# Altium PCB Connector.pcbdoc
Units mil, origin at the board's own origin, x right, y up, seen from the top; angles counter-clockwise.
Board outline 2701.74 x 1475.68 mil, 2 copper layers (Top Layer, Bottom Layer); 8 components, 8 nets, 28 pads, 18 vias.
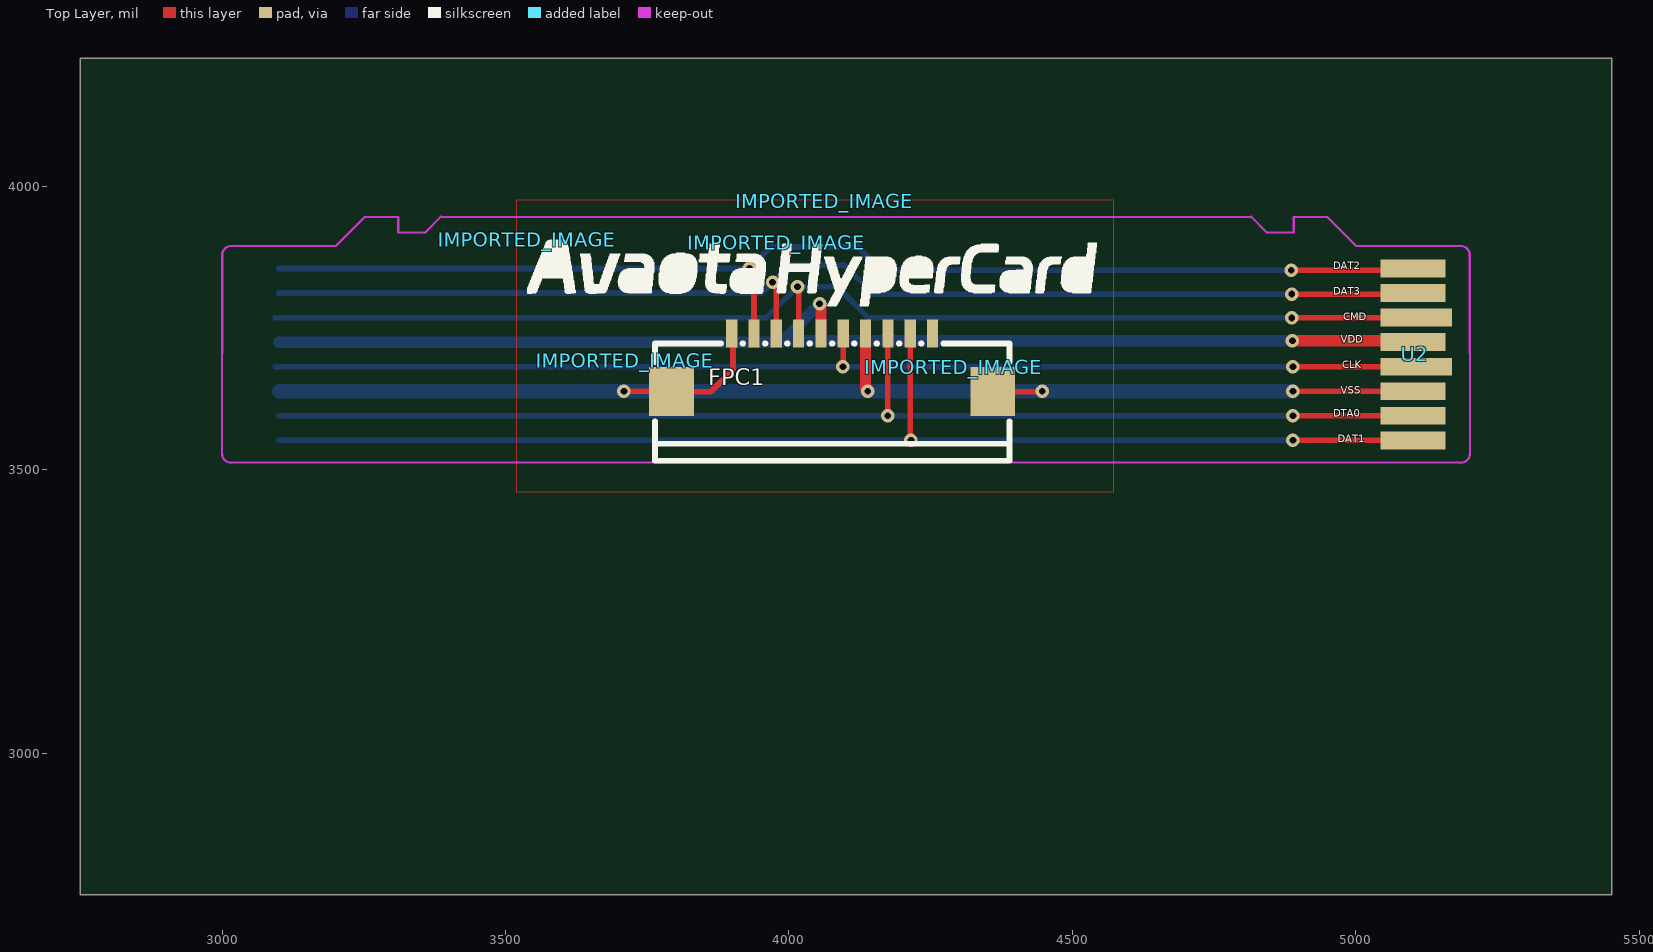
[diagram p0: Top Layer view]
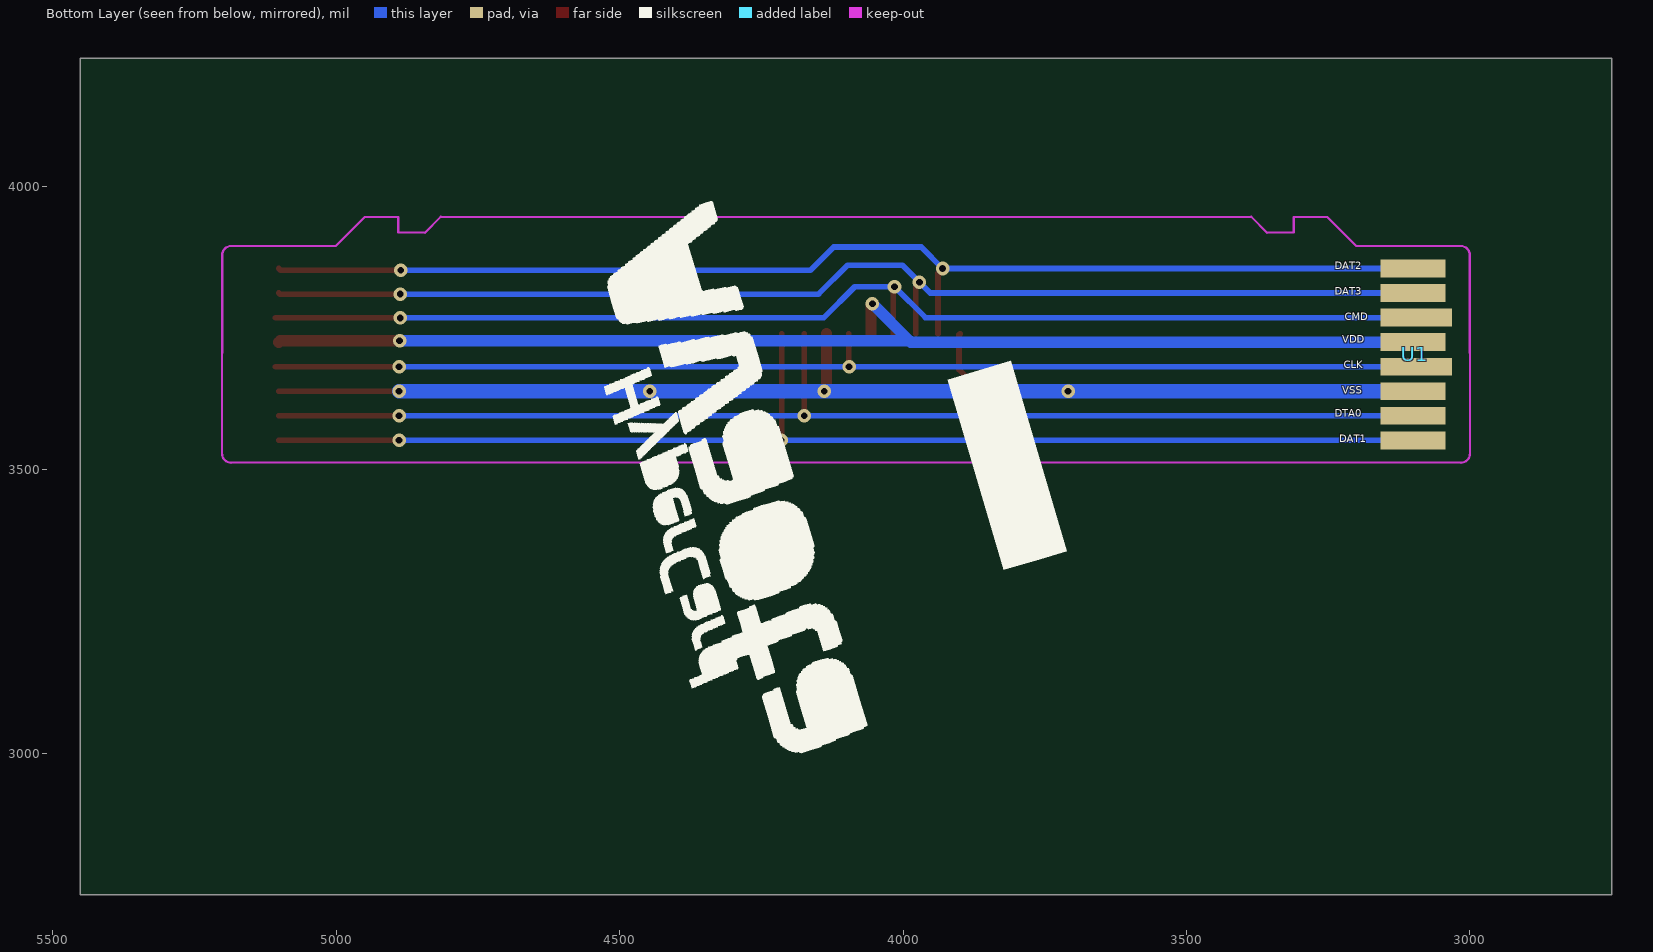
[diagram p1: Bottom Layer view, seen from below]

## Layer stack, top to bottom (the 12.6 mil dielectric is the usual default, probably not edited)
Top Layer: signal copper (thickness not stored)
Dielectric: dielectric 12.6, FR-4, Dk 4.8
Bottom Layer: signal copper (thickness not stored)

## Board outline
5451.74,2750 2750,2750 2750,4225.68 5451.74,4225.68

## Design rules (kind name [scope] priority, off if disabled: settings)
Clearance copperThickness1oz [All] p1: gap=7 ignorepadtopadclearanceinfootprint=FALSE except(4: Track-Track; 6: Track-SMDPad SMDPad-SMDPad Track-THPad SMDPad-THPad THPad-THPad Track-Via SMDPad-Via THPad-Via Via-Via Track-Fill SMDPad-Fill THPad-Fill Via-Fill Fill-Fill SMDPad-Region THPad-Region Via-Region Fill-Region Region-Region Track-Poly SMDPad-Poly THPad-Poly Via-Poly Fill-Poly Poly-Poly Track-Text SMDPad-Text THPad-Text Via-Text Fill-Text Region-Text Poly-Text Text-Text; 6.9: Track-Hole SMDPad-Hole THPad-Hole Via-Hole Fill-Hole Region-Hole Poly-Hole Text-Hole Sheet-Hole; 11.8: Track-Region Region-Poly Track-Sheet SMDPad-Sheet THPad-Sheet Via-Sheet Fill-Sheet Region-Sheet Poly-Sheet Text-Sheet)
Clearance copperThickness2oz [All] p1: gap=7 ignorepadtopadclearanceinfootprint=FALSE except(6: Track-SMDPad SMDPad-SMDPad Track-THPad SMDPad-THPad THPad-THPad Track-Via SMDPad-Via THPad-Via Via-Via Track-Fill SMDPad-Fill THPad-Fill Via-Fill Fill-Fill SMDPad-Region THPad-Region Via-Region Fill-Region Region-Region Track-Poly SMDPad-Poly THPad-Poly Via-Poly Fill-Poly Poly-Poly Track-Text SMDPad-Text THPad-Text Via-Text Fill-Text Region-Text Poly-Text Text-Text; 6.9: Track-Hole SMDPad-Hole THPad-Hole Via-Hole Fill-Hole Region-Hole Poly-Hole Text-Hole Sheet-Hole; 8: Track-Track; 11.8: Track-Region Region-Poly Track-Sheet SMDPad-Sheet THPad-Sheet Via-Sheet Fill-Sheet Region-Sheet Poly-Sheet Text-Sheet)
DiffPairsRouting differentialPair [All] p1: maxuncoupledlength=10 minlimit=0 maxlimit=5.9843 mostfreqgap=5.9843 toplayer_minwidth=5 toplayer_prefwidth=10 toplayer_maxwidth=100 bottomlayer_minwidth=5 bottomlayer_prefwidth=10 bottomlayer_maxwidth=100
PasteMaskExpansion pasteMaskExpansion [All] p1: expansion=0
PlaneConnect innerPlane [All] p1: planeconnectstyle=Relief reliefexpansion=20 reliefentries=4 reliefconductorwidth=10 reliefairgap=10
PolygonConnect copperRegion [All] p1: connectstyle=Relief reliefentries=4 reliefconductorwidth=10 polygonreliefangle="90 Angle" airgapwidth=10
RoutingVias viaSize [All] p1: viastyle="Through Hole" holewidth=12.0078 minholewidth=11.811 maxholewidth=248.0316 width=24.0158 minwidth=19.685 maxwidth=393.7008
SolderMaskExpansion solderMaskExpansion [All] p1: useseparateexpansions=TRUE expansion=2.0079 expansionbottom=2.0079
Width copperThickness1oz [All] p1: maxlimit=100 minlimit=5 preferedwidth=10
Width copperThickness2oz [All] p1: maxlimit=100 minlimit=8 preferedwidth=10

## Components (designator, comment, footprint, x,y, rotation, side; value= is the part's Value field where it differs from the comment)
FPC1 "AFA01-S10FCC-00" FPC-SMD_AFA01-S10FCC-00 4076.37,3688.68 r0 top
IMPORTED_IMAGE "IMPORTED_IMAGE" IMPORTED_IMAGE 4063.67,3973.48 r0 top
IMPORTED_IMAGE "IMPORTED_IMAGE" IMPORTED_IMAGE 4290.94,3680.39 r0 top
IMPORTED_IMAGE "IMPORTED_IMAGE" IMPORTED_IMAGE 3711.13,3691.69 r0 top
IMPORTED_IMAGE "IMPORTED_IMAGE" IMPORTED_IMAGE 3538.37,3905.68 r0 top
IMPORTED_IMAGE "IMPORTED_IMAGE" IMPORTED_IMAGE 3978.37,3900.68 r0 top
U1 "TF Shape" SD卡 3345.37,3731.68 r0 top
U2 "TF Shape" SD卡 4856.37,3731.68 r180 bottom

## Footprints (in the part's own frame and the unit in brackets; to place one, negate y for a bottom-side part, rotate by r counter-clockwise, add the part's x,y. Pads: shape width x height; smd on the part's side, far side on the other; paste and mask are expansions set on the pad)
FPC-SMD_AFA01-S10FCC-00 [mm]
  rect 0.5x1.25 smd: 1(-4.5,1.3) 2(-3.5,1.3) 3(-2.501,1.3) 4(-1.5,1.3) 5(-0.501,1.3) 6(0.499,1.3) 7(1.5,1.3) 8(2.499,1.3) 9(3.5,1.3) 10(4.499,1.3)
  rect 2x2.2 smd: 11(-7.2,-1.3) 12(7.2,-1.3)
  silkscreen extent -7.94,-4.39 7.95,0.86
IMPORTED_IMAGE [mil]
SD卡 [mm]
  rect 2.9x0.8 smd far side: 1(-6.223,3.129) 2(-6.223,2.029) 4(-6.223,-0.171) 6(-6.223,-2.372) 7(-6.223,-3.472) 8(-6.223,-4.572)
  rect 3.2x0.8 smd far side: 3(-6.372,0.928) 5(-6.373,-1.272)
  Board Outline Layer lines w0.1: -8.772,-5.161 -8.762,3.798 -8.772,-5.161 ; -8.372,-5.571 5.868,-5.562 -8.372,-5.571 ; 0.325,4.735 1.034,5.444 0.325,4.735 ; 1.028,5.438 5.828,5.438 1.028,5.438
  Board Outline Layer lines w0.102: -8.772,-5.162 -8.772,-5.062 -8.772,-5.162 ; -8.772,-5.162 ccw(c-8.364,-5.163) -8.372,-5.572 cw(c-8.364,-5.163) -8.772,-5.162 ; -2.372,5.439 -0.871,5.439 ; -2.372,5.439 -0.871,5.439 ; -2.372,5.439 -3.673,4.138 -2.372,5.439 ; -0.871,5.439 -0.871,4.738 -0.871,5.439 ; -8.762,3.738 cw(c-8.362,3.738) -8.362,4.138 ccw(c-8.362,3.738) -8.762,3.738 ; -8.372,4.138 -3.672,4.138 -8.372,4.138 ; -0.873,4.737 0.326,4.737 -0.873,4.737

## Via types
v1: diameter 24.02, hole 12.01, Top Layer to Bottom Layer, 18 vias

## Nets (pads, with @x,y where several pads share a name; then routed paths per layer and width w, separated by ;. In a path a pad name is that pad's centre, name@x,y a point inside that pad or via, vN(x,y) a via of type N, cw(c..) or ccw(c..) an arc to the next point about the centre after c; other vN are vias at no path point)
GND: FPC1.1 FPC1.7 FPC1.11 FPC1.12 U1.6 U2.6 | length 2464.8
  Top Layer w10: v1(3709.02,3638.28) 3792.12,3638.28 FPC1.11 3862.19,3637.5 3901.37,3676.68 3901.37,3737.7 FPC1.1 ; FPC1.12 4446.32,3637.5 v1(4447.11,3638.28) ; v1(4889.37,3638.28) U2.6
  Top Layer w20: FPC1.7 4135.42,3642.24 v1(4139.37,3638.28)
  Bottom Layer w25: U1.6 v1(3709.02,3638.28) v1(4139.37,3638.28) v1(4447.11,3638.28) v1(4889.37,3638.28)
SDC-TF-CLK: FPC1.6 U1.5 U2.5 | length 2071.4
  Top Layer w10: v1(4095.37,3681.68) 4096.02,3682.32 FPC1.6 ; v1(4889.37,3681.68) 5107.19,3681.68 U2.5
  Bottom Layer w10: U1.5 4095.27,3681.58 v1(4095.37,3681.68) v1(4889.37,3681.68)
SDC-TF-CMD: FPC1.4 U1.3 U2.3 | length 2141.9
  Top Layer w10: v1(4015.37,3822.68) 4017.32,3820.73 FPC1.4 ; v1(4887.37,3767.68) 5106.71,3767.68 U2.3
  Bottom Layer w10: U1.3 3960.9,3768.21 v1(4015.37,3822.68) 4085.37,3822.68 4140.37,3767.68 v1(4887.37,3767.68)
SDC-TF-D0: FPC1.8 U1.7 U2.7 | length 2146.1
  Top Layer w10: v1(4174.37,3594.97) 4174.77,3595.37 FPC1.8 ; v1(4889.37,3594.97) U2.7
  Bottom Layer w10: U1.7 v1(4174.37,3594.97) v1(4889.37,3594.97)
SDC-TF-D1: FPC1.9 U1.8 U2.8 | length 2189.7
  Top Layer w10: FPC1.9 4214.17,3552.89 v1(4215.37,3551.68) ; v1(4889.37,3551.68) U2.8
  Bottom Layer w10: U1.8 v1(4215.37,3551.68) v1(4889.37,3551.68)
SDC-TF-D2: FPC1.2 U1.1 U2.1 | length 2153.3
  Top Layer w10: v1(3930.37,3854.85) 3938.57,3846.66 FPC1.2 ; v1(4886.37,3851.68) 5098.18,3851.68 U2.1
  Bottom Layer w10: U1.1 v1(3930.37,3854.85) 3968.2,3892.68 4122.37,3892.68 4163.37,3851.68 v1(4886.37,3851.68)
SDC-TF-D3: FPC1.3 U1.2 U2.2 | length 2136.8
  Top Layer w10: v1(3971.37,3830.68) 3977.92,3824.13 FPC1.3 ; v1(4887.37,3809.68) 5099.51,3809.68 U2.2
  Bottom Layer w10: U1.2 3952.24,3811.55 v1(3971.37,3830.68) 4001.37,3860.68 4098.37,3860.68 4149.37,3809.68 v1(4887.37,3809.68)
VCC-CARD: FPC1.5 U1.4 U2.4 | length 2149.2
  Top Layer w20: v1(4054.37,3792.68) 4056.67,3790.38 FPC1.5 ; v1(4888.37,3727.23) 5099.09,3727.23 U2.4
  Bottom Layer w20: U1.4 3986.65,3724.96 3988.92,3727.23 ; v1(4054.37,3792.68) 3988.92,3727.23 ; v1(4888.37,3727.23) 3988.92,3727.23
pads on no net: FPC1.10

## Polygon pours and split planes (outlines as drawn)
GND on Top Layer (solid, remove dead copper, pour order 0): 3519.37,3460.68 4573.37,3460.68 4573.37,3975.68 3519.37,3975.68

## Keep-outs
Board Outline Layer:
  lines w4: 3574.8,3945.78 4627.27,3945.78 4627.37,3945.68 ; 3576.38,3512.71 4625.36,3512.71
